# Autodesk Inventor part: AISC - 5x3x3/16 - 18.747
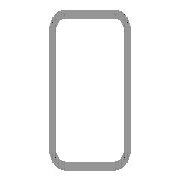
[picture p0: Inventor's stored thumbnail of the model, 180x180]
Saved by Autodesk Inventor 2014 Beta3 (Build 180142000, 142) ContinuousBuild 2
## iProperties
IsCustomPart: 1
Created: 2011-11
Part Number: AISC - 5x3x3/16 - 18.747
Material: Steel, Mild
Description: Tube
Document SubType Name: Modeling
Standard: ANSI
Designer: Thom Tremblay
Standards Organization: ANSI
Language: en-US
Size Designation: 5x3x3/16
Categories: <MemberInstance><Categories><Category DisplayName="Structural Shapes" InternalName="089c4875-fa83-4c05-b084-43b9cc11f5ed" Mnemonic="GRDR"><CategoryParameter Dis
Stock Number: 5x3x3/16
Density: 7.86 g/cm^3
Appearance: Steel
_CCFamilyMember: 33
_CCFamilyDisplayName: ANSI AISC (Rectangular) - Tube
_FrameMemberDoc: Frame Member File
_Version: 15.0.0
_GetPNFromCC: 1
G_L: 18.747 in
G_W: 3.000 in
G_H: 5.000 in
+CF1ADD6C-EB40-4606-989C-EC2802D0A71C+CUTDETAIL1: Cut
+B2A553CF-D4ED-4223-AC76-4A511DF4A8BA+CUTDETAIL2: Cut
Author: Thom Tremblay
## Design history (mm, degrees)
node "Start plane"
node "End plane"
node "Driven Length"
  sketch "Sketch3"
    geometry: L1 (0, 0)-(10, 0) reference
    constraints: 2 end point, 1 horizontal
  workplane "Work Plane3"
  sketch "Sketch4"
    geometry: L1 (-2, 0)-(12, 0) reference; L2 (-53.343, 476.185)-(53.343, 476.185) reference
    dimensions: "d19" = 476.18539 distance between parallel lines of L1 L2 (derived)
sketch "Sweep Path"
  geometry: L1 through (609.6, 0) direction (-1, -0); 1 other entity
  constraints: 5 horizontal
node "Orientation Work Plane"
feature "Body" dims "d20" = 0
workplane "Work Plane5"
sketch "Sketch5"
  geometry: L1 (-38.6, 73.96)-(38.6, 73.96); L2 (-38.6, -73.96)-(38.6, -73.96)
  constraints: 4 end point
feature "LoftSrf1" sketch "Sketch5" dims "d21" = 0, "d22" = 90 deg, "d23" = 0, "d24" = 90 deg
split "Split1"
workplane "Work Plane6"
sketch "Sketch6"
  geometry: L1 (-38.6, 73.96)-(38.6, 73.96); L2 (-38.6, -73.96)-(38.6, -73.96)
  constraints: 4 end point
feature "LoftSrf2" sketch "Sketch6" dims "d25" = 0, "d26" = 90 deg, "d27" = 0, "d28" = 90 deg
split "Split2"
body "Solid1"
sketch "Sketch"
  geometry: L1 (-38.1, -53.975)-(-38.1, 53.975); L2 (-28.575, 63.5)-(28.575, 63.5); L3 (38.1, 53.975)-(38.1, -53.975); L4 (28.575, -63.5)-(-28.575, -63.5); L5 (-28.575, 58.737)-(28.575, 58.737); L6 (33.338, 53.975)-(33.338, -53.975); L7 (28.575, -58.737)-(-28.575, -58.737); L8 (-33.338, -53.975)-(-33.338, 53.975); L9 (0, 36.948)-(0, -36.948); L10 (-23.079, 0)-(23.079, 0); A1 r 9.525 centre (-28.575, -53.975) between (-38.1, -53.975) and (-28.575, -63.5); A2 r 9.525 centre (-28.575, 53.975) between (-28.575, 63.5) and (-38.1, 53.975); A3 r 9.525 centre (28.575, 53.975) between (38.1, 53.975) and (28.575, 63.5); A4 r 9.525 centre (28.575, -53.975) between (28.575, -63.5) and (38.1, -53.975); A5 r 4.763 centre (-28.575, 53.975) between (-28.575, 58.737) and (-33.338, 53.975); A6 r 4.763 centre (28.575, 53.975) between (33.338, 53.975) and (28.575, 58.737); A7 r 4.763 centre (28.575, -53.975) between (28.575, -58.737) and (33.338, -53.975); A8 r 4.763 centre (-28.575, -53.975) between (-33.338, -53.975) and (-28.575, -58.737)
  constraints: 20 end point, 16 point on circle, 8 centre point, 8 tangent, 4 parallel, 3 equal radius, 2 perpendicular, 7 other
  dimensions: "d10" = 127 distance between parallel lines of L2 L4 (= G_H); "d11" = 76.2 distance between parallel lines of L1 L3 (= G_W); "d12" = 4.7625 distance between parallel lines of L3 L6 (= G_T); "d15" = 63.5 distance between parallel lines of L2 L10 (= 0.5 x d10); "d16" = 38.1 distance between parallel lines of L9 L3 (= 0.5 x d11); "d17" = 9.525 radius of A1 (= G_IR)
body "Srf1"
body "Srf2"
other parameters: "G_W" = 76.2 [user parameter; used in 1 equation term], "G_H" = 127 [user parameter; used in 1 equation term], "G_T" = 4.7625 [user parameter; used in 1 equation term], "G_IR" = 9.525 [user parameter; used in 1 equation term], "G_L" = 476.18539 (= d19) [user parameter], "G_OFFSET_START" = 0 [user parameter; used in 1 equation term], "G_OFFSET_END" = 0 [user parameter; used in 1 equation term], "d13" = 0 (computed from G_OFFSET_START), "d14" = 476.18539 (= G_OFFSET_END + B_L), "B_L" = 476.18539 [user parameter; used in 1 equation term], "d18" = 90 deg
